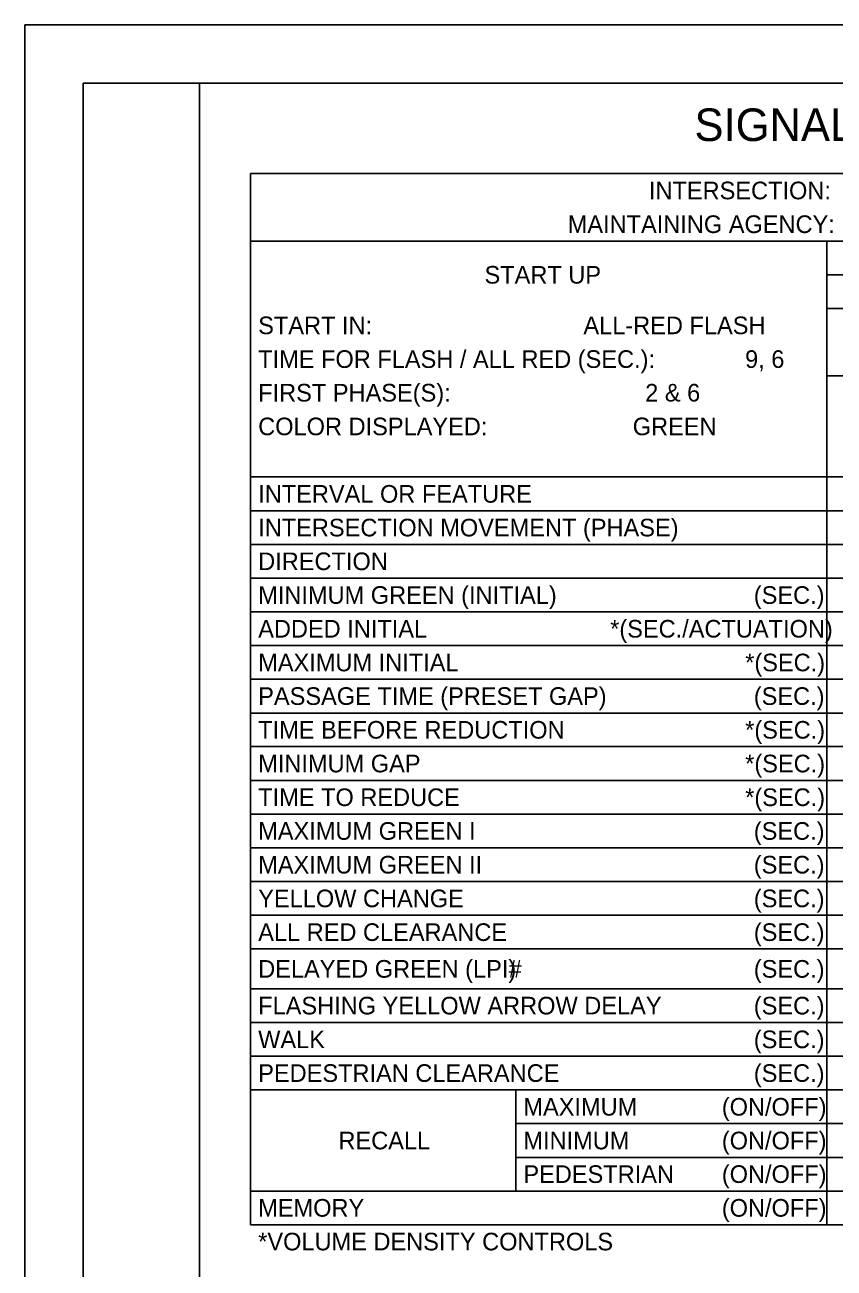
# Model space of a CAD drawing. Extents: x 0 to 34, y 0 to 22.
# Drawn here: x 0 to 6.96, y 11.31 to 22 of the extents above; entities that cross this region are included whole.
import ezdxf

# ---------------------------------------------------------------- set-up
doc = ezdxf.new("R2010")
doc.units = 0
for name, color, linetype in [('SG_P_Text', 7, 'Continuous'), ('SH_Border', 7, 'Continuous'), ('SH_Cut_Line', 7, 'Continuous'), ('SH_Text', 7, 'Continuous')]:
    doc.layers.add(name, color=color, linetype=linetype)

msp = doc.modelspace()

# ---------------------------------------------------------------- linework, layer by layer
at = {"layer": 'SH_Border'}
for points in [[(0.5, 21.5), (1.5, 21.5), (1.5, 0.5), (0.5, 0.5)], [(1.5, 21.5), (33.5, 21.5), (33.5, 0.5), (1.5, 0.5)]]:
    msp.add_lwpolyline(points, close=True, dxfattribs=at)
at = {"layer": 'SH_Cut_Line'}
msp.add_lwpolyline([(0, 0), (34, 0), (34, 22), (0, 22)], close=True, dxfattribs=at)
at = {"layer": 'SH_Text'}
for p, q in [((1.94, 20.721), (6.895, 20.721)), ((1.94, 20.721), (1.94, 20.431)), ((6.895, 20.721), (11.309, 20.721)), ((1.94, 20.431), (1.94, 20.141)), ((1.94, 20.141), (6.895, 20.141)), ((1.94, 20.141), (1.94, 19.851)), ((6.895, 20.141), (11.309, 20.141)), ((6.895, 20.141), (6.895, 19.851)), ((1.94, 19.851), (1.94, 19.561)), ((6.895, 19.851), (11.309, 19.851)), ((6.895, 19.851), (6.895, 19.561)), ((1.94, 19.561), (1.94, 19.271)), ((6.895, 19.561), (11.309, 19.561)), ((6.895, 19.561), (6.895, 19.271)), ((1.94, 19.271), (1.94, 18.981)), ((6.895, 19.271), (6.895, 18.981)), ((1.94, 18.981), (1.94, 18.691)), ((6.895, 18.981), (11.309, 18.981)), ((6.895, 18.981), (6.895, 18.691)), ((1.94, 18.691), (1.94, 18.401)), ((6.895, 18.691), (6.895, 18.401)), ((1.94, 18.401), (1.94, 18.112)), ((6.895, 18.401), (6.895, 18.112)), ((1.94, 18.112), (6.895, 18.112)), ((1.94, 18.112), (1.94, 17.822)), ((6.895, 18.112), (11.309, 18.112)), ((6.895, 18.112), (6.895, 17.822)), ((1.94, 17.822), (6.895, 17.822)), ((1.94, 17.822), (1.94, 17.532)), ((6.895, 17.822), (11.309, 17.822)), ((6.895, 17.822), (6.895, 17.532)), ((1.94, 17.532), (6.895, 17.532)), ((1.94, 17.532), (1.94, 17.242)), ((6.895, 17.532), (11.309, 17.532)), ((6.895, 17.532), (6.895, 17.242)), ((1.94, 17.242), (6.895, 17.242)), ((1.94, 17.242), (1.94, 16.952)), ((6.895, 17.242), (11.309, 17.242)), ((6.895, 17.242), (6.895, 16.952)), ((1.94, 16.952), (6.895, 16.952)), ((1.94, 16.952), (1.94, 16.662)), ((6.895, 16.952), (11.309, 16.952)), ((6.895, 16.952), (6.895, 16.662)), ((1.94, 16.662), (6.895, 16.662)), ((1.94, 16.662), (1.94, 16.372)), ((6.895, 16.662), (11.309, 16.662)), ((6.895, 16.662), (6.895, 16.372)), ((1.94, 16.372), (6.895, 16.372)), ((1.94, 16.372), (1.94, 16.082)), ((6.895, 16.372), (11.309, 16.372)), ((6.895, 16.372), (6.895, 16.082)), ((1.94, 16.082), (6.895, 16.082)), ((1.94, 16.082), (1.94, 15.793)), ((6.895, 16.082), (11.309, 16.082)), ((6.895, 16.082), (6.895, 15.793)), ((1.94, 15.793), (6.895, 15.793)), ((1.94, 15.793), (1.94, 15.503)), ((6.895, 15.793), (11.309, 15.793)), ((6.895, 15.793), (6.895, 15.503)), ((1.94, 15.503), (6.895, 15.503)), ((1.94, 15.503), (1.94, 15.213)), ((6.895, 15.503), (11.309, 15.503)), ((6.895, 15.503), (6.895, 15.213)), ((1.94, 15.213), (6.895, 15.213)), ((1.94, 15.213), (1.94, 14.923)), ((6.895, 15.213), (11.309, 15.213)), ((6.895, 15.213), (6.895, 14.923)), ((1.94, 14.923), (6.895, 14.923)), ((1.94, 14.923), (1.94, 14.633)), ((6.895, 14.923), (11.309, 14.923)), ((6.895, 14.923), (6.895, 14.633)), ((1.94, 14.633), (6.895, 14.633)), ((1.94, 14.633), (1.94, 14.343)), ((6.895, 14.633), (11.309, 14.633)), ((6.895, 14.633), (6.895, 14.343)), ((1.94, 14.343), (6.895, 14.343)), ((1.94, 14.343), (1.94, 14.053)), ((6.895, 14.343), (11.309, 14.343)), ((6.895, 14.343), (6.895, 14.053)), ((1.94, 14.053), (6.895, 14.053)), ((1.94, 14.053), (1.94, 13.711)), ((6.895, 14.053), (11.309, 14.053)), ((6.895, 14.053), (6.895, 13.711)), ((1.94, 13.711), (6.895, 13.711)), ((1.94, 13.711), (1.94, 13.421)), ((6.895, 13.711), (11.309, 13.711)), ((6.895, 13.711), (6.895, 13.421)), ((1.94, 13.421), (6.895, 13.421)), ((1.94, 13.421), (1.94, 12.841)), ((6.895, 13.421), (11.309, 13.421)), ((6.895, 13.421), (6.895, 12.841)), ((1.94, 13.131), (6.895, 13.131)), ((6.895, 13.131), (11.309, 13.131)), ((1.94, 12.841), (6.895, 12.841)), ((1.94, 12.841), (1.94, 12.551)), ((4.22, 12.841), (4.22, 12.551)), ((6.895, 12.841), (11.309, 12.841)), ((6.895, 12.841), (6.895, 12.551)), ((1.94, 12.551), (1.94, 12.261)), ((4.22, 12.551), (6.895, 12.551)), ((4.22, 12.551), (4.22, 12.261)), ((6.895, 12.551), (11.309, 12.551)), ((6.895, 12.551), (6.895, 12.261)), ((1.94, 12.261), (1.94, 11.971)), ((4.22, 12.261), (6.895, 12.261)), ((4.22, 12.261), (4.22, 11.971)), ((6.895, 12.261), (11.309, 12.261)), ((6.895, 12.261), (6.895, 11.971)), ((1.94, 11.971), (6.895, 11.971)), ((1.94, 11.971), (1.94, 11.681)), ((6.895, 11.971), (11.309, 11.971)), ((6.895, 11.971), (6.895, 11.681)), ((1.94, 11.681), (6.895, 11.681)), ((6.895, 11.681), (11.309, 11.681))]:
    msp.add_line(p, q, dxfattribs=at)

# ---------------------------------------------------------------- texts
at = {"layer": 'SG_P_Text'}
msp.add_text('SIGNAL TIMING CHART', height=0.28, dxfattribs=at).set_placement((5.757, 21.001))
at = {"layer": 'SH_Text'}
for s, height, p in [('INTERSECTION:', 0.15153, (5.365, 20.5)), ('MAINTAINING AGENCY:', 0.15153, (4.667, 20.21)), ('START UP', 0.1515, (3.952, 19.775)), ('START IN:', 0.1515, (2.006, 19.34)), ('ALL-RED FLASH', 0.15153, (4.802, 19.34)), ('TIME FOR FLASH / ALL RED (SEC.):', 0.15153, (2.006, 19.05)), ('9, 6', 0.1515, (6.192, 19.05)), ('FIRST PHASE(S):', 0.15153, (2.006, 18.761)), ('2 & 6', 0.1515, (5.333, 18.761)), ('COLOR DISPLAYED:', 0.15153, (2.006, 18.471)), ('GREEN', 0.1515, (5.226, 18.471)), ('INTERVAL OR FEATURE', 0.15153, (2.006, 17.891)), ('INTERSECTION MOVEMENT (PHASE)', 0.15153, (2.006, 17.601)), ('DIRECTION', 0.1515, (2.006, 17.311)), ('MINIMUM GREEN (INITIAL)', 0.15153, (2.006, 17.021)), ('(SEC.)', 0.1515, (6.267, 17.021)), ('ADDED INITIAL', 0.15153, (2.006, 16.731)), ('*(SEC./ACTUATION)', 0.15153, (5.032, 16.731)), ('MAXIMUM INITIAL', 0.15153, (2.006, 16.441)), ('*(SEC.)', 0.1515, (6.193, 16.441)), ('PASSAGE TIME (PRESET GAP)', 0.15153, (2.006, 16.152)), ('(SEC.)', 0.1515, (6.267, 16.152)), ('TIME BEFORE REDUCTION', 0.15153, (2.006, 15.862)), ('*(SEC.)', 0.1515, (6.193, 15.862)), ('MINIMUM GAP', 0.15153, (2.006, 15.572)), ('*(SEC.)', 0.1515, (6.193, 15.572)), ('TIME TO REDUCE', 0.15153, (2.006, 15.282)), ('*(SEC.)', 0.1515, (6.193, 15.282)), ('MAXIMUM GREEN I', 0.15153, (2.006, 14.992)), ('(SEC.)', 0.1515, (6.267, 14.992)), ('(SEC.)', 0.1515, (6.267, 14.702)), ('MAXIMUM GREEN II', 0.15153, (2.006, 14.702)), ('YELLOW CHANGE', 0.15153, (2.006, 14.412)), ('(SEC.)', 0.1515, (6.267, 14.412)), ('ALL RED CLEARANCE', 0.15153, (2.006, 14.122)), ('(SEC.)', 0.1515, (6.267, 14.122)), ('DELAYED GREEN (LPI) ', 0.15153, (2.006, 13.806)), ('#', 0.152, (4.159, 13.806)), ('(SEC.)', 0.1515, (6.267, 13.806)), ('FLASHING YELLOW ARROW DELAY', 0.15153, (2.006, 13.49)), ('(SEC.)', 0.1515, (6.267, 13.49)), ('WALK', 0.1515, (2.006, 13.2)), ('(SEC.)', 0.1515, (6.267, 13.2)), ('PEDESTRIAN CLEARANCE', 0.15153, (2.006, 12.91)), ('(SEC.)', 0.1515, (6.267, 12.91)), ('MAXIMUM', 0.1515, (4.286, 12.62)), ('(ON/OFF)', 0.1515, (5.992, 12.62)), ('RECALL', 0.1515, (2.696, 12.33)), ('MINIMUM', 0.1515, (4.286, 12.33)), ('(ON/OFF)', 0.1515, (5.992, 12.33)), ('PEDESTRIAN', 0.1515, (4.286, 12.041)), ('(ON/OFF)', 0.1515, (5.992, 12.041)), ('MEMORY', 0.1515, (2.006, 11.751)), ('(ON/OFF)', 0.1515, (5.992, 11.751)), ('*VOLUME DENSITY CONTROLS', 0.15153, (2.006, 11.461))]:
    msp.add_text(s, height=height, dxfattribs=at).set_placement(p)

doc.saveas('drawing.dxf')
